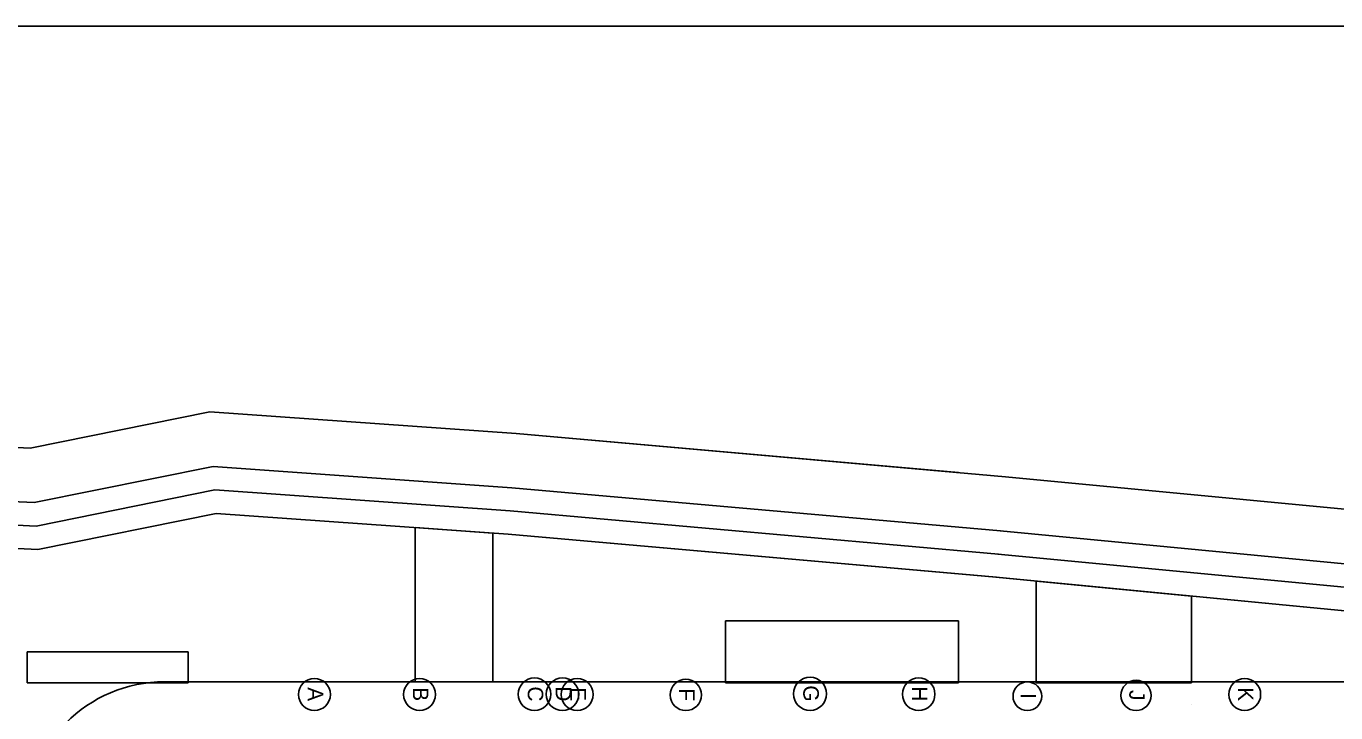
# Model space of a CAD drawing. Extents: x -264165 to -263575, y -1242333 to -1242036.
# Drawn here: x -263927 to -263842.7, y -1242080.3 to -1242036.1 of the extents above; entities that cross this region are included whole.
import ezdxf

# ---------------------------------------------------------------- set-up
doc = ezdxf.new("R2010")
doc.units = 0
for name, color, linetype in [('KFA_HESCON_OSI_STAVBY', 7, 'Continuous'), ('KFA_SITUACIA_DRS_VYTYCOVAK_SEDA', 7, 'Continuous'), ('RAM_NA_TLAC', 7, 'Continuous')]:
    doc.layers.add(name, color=color, linetype=linetype)

msp = doc.modelspace()

# ---------------------------------------------------------------- linework, layer by layer
at = {"layer": 'KFA_HESCON_OSI_STAVBY'}
msp.add_line((-263851.968, -1242079.752), (-263851.968, -1242079.752), dxfattribs=at)
for centre, radius in [((-263908.458, -1242079.124), 1.027), ((-263901.683, -1242079.124), 1.027), ((-263894.283, -1242079.111), 1.047), ((-263892.483, -1242079.111), 1.047), ((-263891.533, -1242079.124), 1.027), ((-263884.533, -1242079.155), 1.008), ((-263876.533, -1242079.082), 1.068), ((-263869.533, -1242079.111), 1.047), ((-263862.533, -1242079.239), 0.925), ((-263855.533, -1242079.188), 0.974), ((-263848.533, -1242079.124), 1.027)]:
    msp.add_circle(centre, radius, dxfattribs=at)
at = {"layer": 'KFA_SITUACIA_DRS_VYTYCOVAK_SEDA'}
for p, q in [((-263915.197, -1242060.92), (-263926.771, -1242063.254)), ((-263915.197, -1242060.92), (-263926.771, -1242063.254)), ((-263895.455, -1242062.322), (-263915.197, -1242060.92)), ((-263895.455, -1242062.322), (-263915.197, -1242060.92)), ((-263926.771, -1242063.254), (-263950.745, -1242062.149)), ((-263926.771, -1242063.254), (-263950.745, -1242062.149)), ((-263866.964, -1242064.823), (-263895.455, -1242062.322)), ((-263863.949, -1242065.106), (-263895.455, -1242062.322)), ((-263914.971, -1242064.445), (-263926.501, -1242066.77)), ((-263895.733, -1242065.811), (-263914.971, -1242064.445)), ((-263926.501, -1242066.77), (-263951.337, -1242065.625)), ((-263864.257, -1242068.593), (-263895.733, -1242065.811)), ((-263765.318, -1242074.565), (-263863.949, -1242065.106)), ((-263914.874, -1242065.956), (-263926.386, -1242068.277)), ((-263895.852, -1242067.306), (-263914.874, -1242065.956)), ((-263926.386, -1242068.277), (-263951.591, -1242067.115)), ((-263914.777, -1242067.467), (-263926.271, -1242069.783)), ((-263914.777, -1242067.467), (-263926.271, -1242069.783)), ((-263895.971, -1242068.802), (-263914.777, -1242067.467)), ((-263895.971, -1242068.802), (-263914.777, -1242067.467)), ((-263864.389, -1242070.087), (-263895.852, -1242067.306)), ((-263926.271, -1242069.783), (-263951.845, -1242068.605)), ((-263926.271, -1242069.783), (-263951.845, -1242068.605)), ((-263901.968, -1242068.376), (-263901.968, -1242078.308)), ((-263901.968, -1242068.376), (-263896.968, -1242068.731)), ((-263896.968, -1242068.731), (-263901.968, -1242068.376)), ((-263901.968, -1242068.376), (-263901.968, -1242074.382)), ((-263896.968, -1242078.308), (-263896.968, -1242068.731)), ((-263896.968, -1242074.382), (-263896.968, -1242068.731)), ((-263864.546, -1242071.579), (-263895.971, -1242068.802)), ((-263864.521, -1242071.581), (-263895.971, -1242068.802)), ((-263765.364, -1242078.076), (-263864.283, -1242068.59)), ((-263766.58, -1242079.467), (-263864.426, -1242070.084)), ((-263765.366, -1242081.09), (-263864.57, -1242071.577)), ((-263766.58, -1242080.973), (-263864.546, -1242071.579)), ((-263861.968, -1242078.382), (-263861.968, -1242071.826)), ((-263861.968, -1242071.826), (-263851.968, -1242072.785)), ((-263861.968, -1242078.382), (-263861.968, -1242071.826)), ((-263861.968, -1242071.826), (-263851.968, -1242072.785)), ((-263851.968, -1242072.785), (-263851.968, -1242078.382)), ((-263851.968, -1242072.785), (-263851.968, -1242078.382)), ((-263901.968, -1242074.382), (-263901.968, -1242078.308)), ((-263896.968, -1242078.308), (-263896.968, -1242074.382)), ((-263881.968, -1242074.382), (-263866.968, -1242074.382)), ((-263881.968, -1242078.382), (-263881.968, -1242074.382)), ((-263881.968, -1242074.382), (-263866.968, -1242074.382)), ((-263881.968, -1242078.382), (-263881.968, -1242074.382)), ((-263866.968, -1242074.382), (-263866.968, -1242078.382)), ((-263866.968, -1242074.382), (-263866.968, -1242078.382)), ((-263926.968, -1242076.382), (-263921.968, -1242076.382)), ((-263926.968, -1242078.382), (-263926.968, -1242076.382)), ((-263926.968, -1242076.382), (-263916.593, -1242076.382)), ((-263926.968, -1242078.382), (-263926.968, -1242076.382)), ((-263921.968, -1242076.382), (-263916.593, -1242076.382)), ((-263916.593, -1242076.382), (-263916.593, -1242078.382)), ((-263916.593, -1242076.382), (-263916.593, -1242078.382)), ((-263921.968, -1242078.382), (-263926.968, -1242078.382)), ((-263916.593, -1242078.382), (-263926.968, -1242078.382)), ((-263916.593, -1242078.382), (-263921.968, -1242078.382)), ((-263918.093, -1242078.308), (-263807.725, -1242078.308)), ((-263901.968, -1242078.308), (-263896.968, -1242078.308)), ((-263901.968, -1242078.308), (-263896.968, -1242078.308)), ((-263866.968, -1242078.382), (-263881.968, -1242078.382)), ((-263866.968, -1242078.382), (-263881.968, -1242078.382)), ((-263851.968, -1242078.382), (-263861.968, -1242078.382)), ((-263851.968, -1242078.382), (-263861.968, -1242078.382))]:
    msp.add_line(p, q, dxfattribs=at)
msp.add_arc((-263918.093, -1242087.308), 9, 90, 180, dxfattribs=at)
at = {"layer": 'RAM_NA_TLAC'}
msp.add_lwpolyline([(-264165.158, -1242333.092), (-264165.158, -1242036.092), (-263955.158, -1242036.092), (-263575.158, -1242036.092), (-263575.158, -1242333.092), (-263955.158, -1242333.092)], close=True, dxfattribs=at)

# ---------------------------------------------------------------- texts
at = {"layer": 'KFA_HESCON_OSI_STAVBY'}
for s, p in [('A', (-263908.893, -1242078.659)), ('B', (-263902.118, -1242078.659)), ('C', (-263894.718, -1242078.607)), ('D', (-263892.918, -1242078.607)), ('E', (-263891.968, -1242078.659)), ('F', (-263884.968, -1242078.729)), ('G', (-263876.968, -1242078.539)), ('H', (-263869.968, -1242078.607)), ('I', (-263862.968, -1242079.045)), ('J', (-263855.968, -1242078.839)), ('K', (-263848.968, -1242078.659))]:
    msp.add_text(s, height=1, rotation=270, dxfattribs=at).set_placement(p)

doc.saveas('drawing.dxf')
